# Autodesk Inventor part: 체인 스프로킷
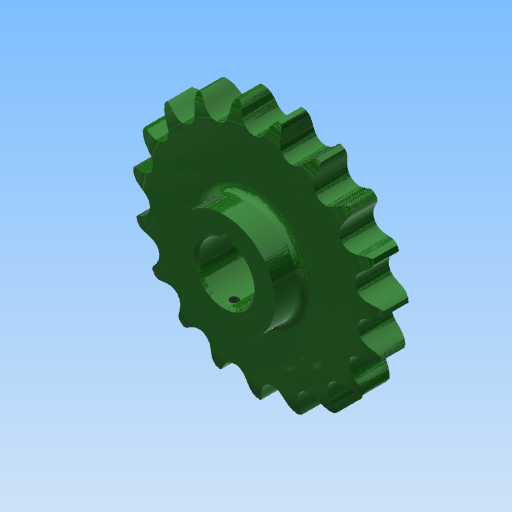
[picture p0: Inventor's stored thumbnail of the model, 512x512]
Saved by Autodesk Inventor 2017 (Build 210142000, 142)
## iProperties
Created: 2013-01
Part Number: 체인 스프로킷
Material: 강철, 연강
Document SubType Name: Modeling
Designer: mdu
Density: 1 g/cm^3
Appearance: 매끄러움 - 짙은 산림 녹색
CustomPartVersion: 1
Author: mdu
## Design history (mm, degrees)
sketch "이론적 톱니 프로파일"
  geometry: L1 (0, 0)-(0, 45.567); L2 (0, 0)-(14.795, 43.098); L3 (0, 45.567)-(14.795, 43.098); L4 (0, 45.567)-(5.661, 50.015); L5 (5.661, 50.015)-(-5.141, 45.406); L6 (-12.428, 43.493)-(-5.573, 46.417); L7 (-5.141, 45.406)-(-5.573, 46.417); L8 (5.573, 46.417)-(5.141, 45.406); L9 (0, 0)-(8.138, 48.771); A1 r 45.567 centre (0, 0) between (0, 45.567) and (14.795, 43.098); A2 r 49.445 centre (0, 0) between (7.302, 48.903) and (-7.302, 48.903); A3 r 4.545 centre (0, 45.567) between (-3.574, 42.758) and (3.574, 42.758); A4 r 7.453 centre (12.428, 43.493) between (7.302, 48.903) and (5.573, 46.417); A5 r 7.453 centre (-12.428, 43.493) between (-5.573, 46.417) and (-7.302, 48.903); A6 r 11.745 centre (5.661, 50.015) between (-5.141, 45.406) and (-3.574, 42.758); A7 r 11.745 centre (-5.661, 50.015) between (3.574, 42.758) and (5.141, 45.406); 2 further points
  constraints: 18 end point, 15 point on circle, 7 centre point, 3 coincident, 3 point on line, 3 symmetric about line, 3 tangent, 1 equal radius, 1 midpoint, 1 parallel, 1 vertical, 1 other
  dimensions: "d0" = 91.13301 diameter of A1 (computed from da_p, da_z); "d2" = 18.9474 deg angle of L2 L1 (computed from da_z); "d3" = 4.545 radius of A3 (= 0.5 x da_Dr + da_SC); "d10" = 128.158 deg angle of L4 L1 (computed from da_z); "d11" = 15.0526 deg angle of L5 L4 (computed from da_z); "d12" = 7.2 distance of L3.start L4.end (= 0.8 x da_Dr); "d13" = 11.745 distance of L4.end L5.end (= 1.3 x da_Dr + da_SC); "d14" = 12.6 distance of A4.centre L1.end (= 1.4 x da_Dr); "d23" = 4.5 distance from line of L9.end L3 (= da_Ha)
sketch "톱니 프로파일"
  geometry: L1 (0, 0)-(0, 45.567); L2 (0, 45.567)-(4.203, 43.837); L3 (0, 45.567)-(-4.203, 43.837); A1 r 4.545 centre (0, 45.567) between (-4.203, 43.837) and (4.203, 43.837); A2 r 22.68 centre (25.176, 35.206) between (7.12, 48.93) and (4.203, 43.837); A3 r 22.68 centre (-25.176, 35.206) between (-4.203, 43.837) and (-7.12, 48.93); A4 r 49.445 centre (0, 0) between (-7.12, 48.93) and (7.12, 48.93) reference; 1 further point
  constraints: 9 point on circle, 6 end point, 3 centre point, 2 tangent, 1 coincident, 1 equal radius, 1 vertical, 1 other
  dimensions: "d44" = 135.263 deg angle of L3 L2 (= da_Alfa); "d45" = 22.68 radius of A2 (= da_Re); "d46" = 4.545 radius of A1 (= da_Ri)
sketch "단면 프로파일"
  geometry: L1 (49.445, 0)-(-49.445, 0) reference; L2 (33.265, 6.65)-(-33.265, 6.65); L3 (-33.265, 6.65)-(-33.265, -6.65); L4 (-33.265, -6.65)-(33.265, -6.65); L5 (33.265, -6.65)-(33.265, 6.65); L6 (33.265, 6.65)-(49.445, 6.65); L7 (49.445, 6.65)-(49.445, -6.65); L8 (49.445, -6.65)-(33.265, -6.65); L9 (33.265, -6.65)-(33.265, 6.65); L10 (42.183, 6.65)-(0, 6.65); L11 (0, 6.65)-(0, -6.65); L12 (0, -6.65)-(42.183, -6.65); L13 (0, 6.65)-(0, -6.65); L14 (49.445, 4.775)-(49.445, -4.775); A1 r 15 centre (42.183, -8.35) between (49.445, 4.775) and (42.183, 6.65); A2 r 15 centre (42.183, 8.35) between (42.183, -6.65) and (49.445, -4.775); 2 further points
  constraints: 26 end point, 7 midpoint, 5 perpendicular, 4 parallel, 4 point on circle, 3 point on line, 3 symmetric about line, 2 centre point, 2 horizontal, 2 tangent, 1 collinear, 1 other
  dimensions: "d30" = 13.3 distance between parallel lines of L8 L6 (= da_Bf); "d31" = 66.53007 distance between parallel lines of L3 L5 (= da_Ds); "d32" = 13.3 distance between parallel lines of L4 L2 (= da_Bs); "d33" = 1.875 distance from line of L14.start L6 (= da_Ba); "d34" = 15 radius of A1 (= da_Rx); "d43" = 6.65 distance between parallel lines of L4 L1 (computed from da_k, da_pt, da_Bs)
revolve "슈라우드" stored, may be unused: angle "d36" = 90 deg
revolve "스트랜드" stored, may be unused: angle "d37" = 90 deg
extrude "이론적 톱니" cut sketch "이론적 톱니 프로파일" stored distance "d18" = 10; taper "d19" = 0 deg; dims "d49" = 0, "form_type" = 0 [user parameter]
extrude "톱니" cut sketch "톱니 프로파일" stored distance "d47" = 10; taper "d48" = 0 deg; dims "d50" = 10, "form_type" = 0 [user parameter]
node "타이밍 평면"
node "작업 평면3"
sketch "스케치5"
  geometry: C1 r 20 at (0, -45.567); 1 further point
  constraints: 1 centre point, 1 coincident
  dimensions: "d52" = 40 diameter of C1
extrude "돌출4" join sketch "스케치5" stored distance "d53" = 10; taper "d54" = 0 deg
sketch "스케치6"
  geometry: L1 (3, 10.583)-(3, 13.8); L2 (3, 13.8)-(-3, 13.8); L3 (-3, 13.8)-(-3, 10.583); A1 r 11 centre (0, 0) between (3, 10.583) and (-3, 10.583); 1 further point
  constraints: 6 end point, 2 parallel, 2 point on circle, 1 centre point, 1 coincident, 1 perpendicular, 1 vertical
  dimensions: "d55" = 22 diameter of A1; "d56" = 24.8 dimension on A1 L2 (computed from d55); "d57" = 6 distance of L1.end L2.end
extrude "돌출5" cut sketch "스케치6" stored distance "d58" = 10; taper "d59" = 0 deg
fillet "모깎기2" dims "d60" = 3
chamfer "모따기1" distance "d61" = 1; stored, may be unused: second distance "d62" = 2, angle "d63" = 45 deg
node "작업 평면4"
sketch "스케치7"
  geometry: L1 (20, 11.7)-(-20, 11.7) reference; 2 further points
  constraints: 1 vertical alignment
  dimensions: "d64" = 4 distance from line of L1 point (0, 7.7)
hole "구멍1" sketch "스케치7" at (0, 7.7) diameter "d65" = 3.242; stored, may be unused: countersink angle "d69" = 90 deg, drill point angle "d71" = 118 deg; dims "d66" = 6, "d67" = 4, "d68" = 2, "d70" = 8
body "Solid1"
pattern_linear "스트랜드 패턴" dims "d40" = 24 (= da_pt)
pattern_circular "톱니 패턴" dims angle "d21" = 360 deg
other parameters: "da_p" = 15 [user parameter; used in 1 equation term], "da_Dr" = 9 [user parameter; used in 4 equation terms], "da_SC" = 0.045 [user parameter; used in 2 equation terms], "da_Ha" = 4.5 [user parameter; used in 1 equation term], "da_pt" = 24 [user parameter; used in 2 equation terms], "da_Bf" = 13.3 [user parameter; used in 1 equation term], "d28" = 0, "d29" = 0, "da_Ba" = 1.875 [user parameter; used in 1 equation term], "da_Rx" = 15 [user parameter; used in 1 equation term], "da_Ra" = 0.6 [user parameter], "da_Bs" = 13.3 [user parameter; used in 2 equation terms], "da_Ds" = 66.53007 [user parameter; used in 1 equation term], "d42" = 0, "da_Re" = 22.68 [user parameter; used in 1 equation term], "da_Ri" = 4.545 [user parameter; used in 1 equation term], "da_Alfa" = 135.263 deg [user parameter; used in 1 equation term], "d51" = -25
